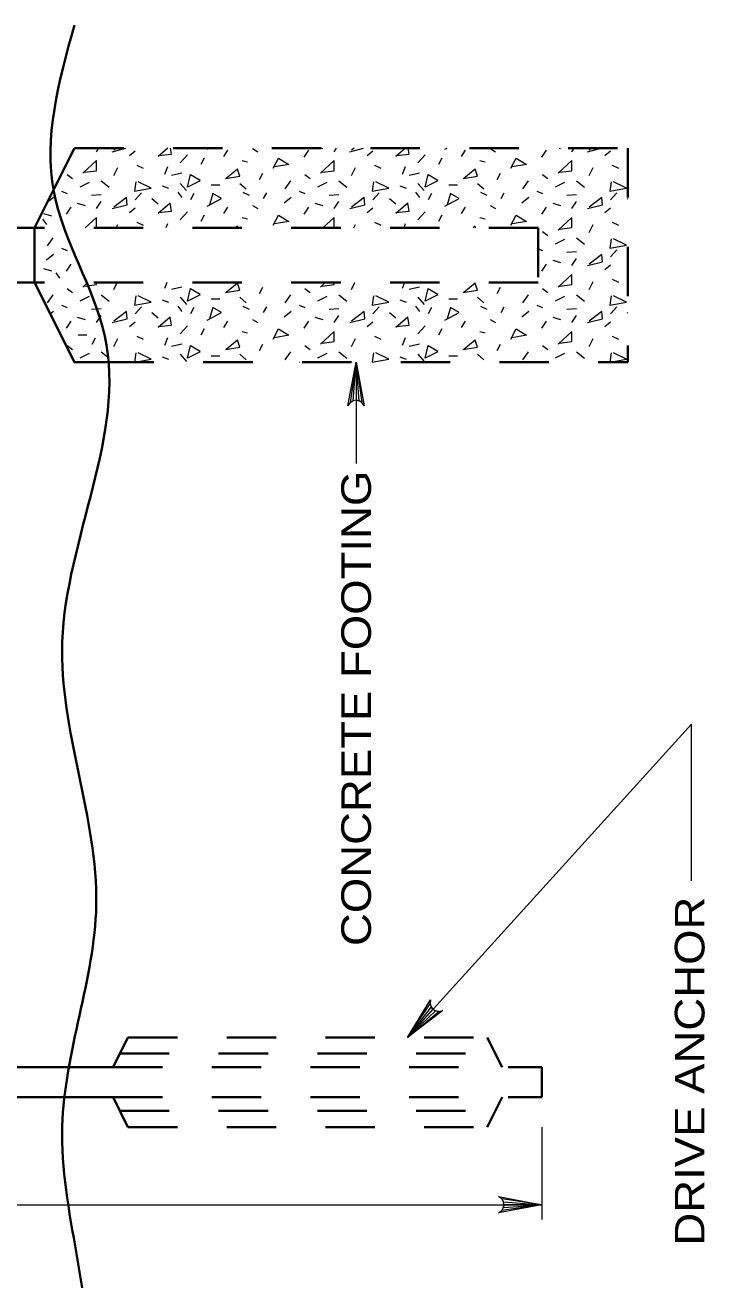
# Model space of a CAD drawing. Extents: x -46.1 to -39.3, y 101.7 to 111.8.
# Drawn here: x -43.099 to -41.722, y 109.249 to 111.793 of the extents above; entities that cross this region are included whole.
import ezdxf
from ezdxf.enums import TextEntityAlignment as Align

# ---------------------------------------------------------------- set-up
doc = ezdxf.new("R2010")
doc.units = 0
doc.header["$LTSCALE"] = 0.024
doc.linetypes.add('SHORT_DASHED', pattern=[2.7, 1.5, -1.2])
for name, color, linetype, lineweight in [('1', 7, 'Continuous', 35), ('10', 7, 'Continuous', 13), ('12', 7, 'Continuous', 53), ('6', 7, 'Continuous', 13)]:
    doc.layers.add(name, color=color, linetype=linetype, lineweight=lineweight)

msp = doc.modelspace()

# ---------------------------------------------------------------- linework, layer by layer
at = {"layer": '1', "linetype": 'SHORT_DASHED'}
for p, q in [((-42.99933, 111.54375), (-43.04037, 111.46167)), ((-42.99933, 111.54375), (-41.87812, 111.54375)), ((-41.87812, 111.54375), (-41.87812, 111.10942)), ((-42.05994, 111.38215), (-43.08015, 111.38215)), ((-42.05994, 111.38215), (-42.05994, 111.27102)), ((-42.05994, 111.27102), (-43.08015, 111.27102)), ((-42.93817, 111.10942), (-41.87812, 111.10942)), ((-42.89075, 109.74073), (-42.92104, 109.68012)), ((-42.89075, 109.74073), (-42.16348, 109.74073)), ((-42.16348, 109.74073), (-42.13317, 109.68012)), ((-42.90715, 109.7079), (-42.14706, 109.7079)), ((-42.92104, 109.68012), (-43.01042, 109.68012)), ((-42.92104, 109.68012), (-42.05235, 109.68012)), ((-42.05235, 109.68012), (-42.05235, 109.6195)), ((-42.92104, 109.6195), (-43.01954, 109.6195)), ((-42.92104, 109.6195), (-42.05235, 109.6195)), ((-42.92104, 109.6195), (-42.89075, 109.5589)), ((-42.13317, 109.6195), (-42.16348, 109.5589)), ((-42.90715, 109.59173), (-42.14706, 109.59173)), ((-42.89075, 109.5589), (-42.16348, 109.5589))]:
    msp.add_line(p, q, dxfattribs=at)
at = {"layer": '1'}
for p, q in [((-43.04037, 111.46167), (-43.08015, 111.38215)), ((-45.05994, 111.38215), (-43.08015, 111.38215)), ((-43.08015, 111.27102), (-43.08015, 111.38215)), ((-43.18873, 111.27102), (-43.08015, 111.27102)), ((-44.91852, 109.68012), (-43.01042, 109.68012)), ((-44.91852, 109.6195), (-43.01954, 109.6195))]:
    msp.add_line(p, q, dxfattribs=at)
msp.add_lwpolyline([(-43.08015, 111.27102), (-42.99933, 111.10942), (-42.93817, 111.10942)], dxfattribs=at)
msp.add_spline([(-42.99933, 111.7931), (-43.04115, 111.45546), (-42.93785, 111.16262), (-43.02392, 110.54252), (-42.95506, 110.00852), (-43.02392, 109.56067), (-42.97227, 109.0439), (-43.04115, 108.68217), (-42.95506, 108.18263), (-43.04115, 107.1491), (-42.97227, 106.47729), (-43.04115, 105.66771), (-42.97227, 104.927), (-43.00671, 104.25521), (-43.00256, 103.82462)], degree=3, dxfattribs=at)
at = {"layer": '10'}
for p, q in [((-42.42867, 111.10942), (-42.42867, 110.90398)), ((-42.05235, 109.5589), (-42.05235, 109.37133)), ((-44.98417, 109.40162), (-42.05235, 109.40162))]:
    msp.add_line(p, q, dxfattribs=at)
for points in [[(-42.42867, 111.10942), (-42.4121, 111.02115), (-42.41683, 111.02794), (-42.42275, 111.03146), (-42.42867, 111.03246), (-42.43458, 111.03146), (-42.4405, 111.02794), (-42.44521, 111.02115), (-42.42867, 111.10942), (-42.4405, 111.02794), (-42.43458, 111.03146), (-42.42867, 111.10942), (-42.42867, 111.03246), (-42.42275, 111.03146), (-42.42867, 111.10942), (-42.41683, 111.02794)], [(-41.74944, 110.05842), (-41.74944, 110.37596), (-42.32471, 109.74073)], [(-42.32471, 109.74073), (-42.27773, 109.81725), (-42.27879, 109.80904), (-42.27677, 109.80248), (-42.27306, 109.79775), (-42.268, 109.79454), (-42.26125, 109.79317), (-42.25319, 109.79504), (-42.32471, 109.74073), (-42.26125, 109.79317), (-42.268, 109.79454), (-42.32471, 109.74073), (-42.27306, 109.79775), (-42.27677, 109.80248), (-42.32471, 109.74073), (-42.27879, 109.80904)], [(-42.05235, 109.40162), (-42.14062, 109.38508), (-42.13381, 109.38979), (-42.13031, 109.39571), (-42.12929, 109.40162), (-42.13031, 109.40756), (-42.13381, 109.41348), (-42.14062, 109.41819), (-42.05235, 109.40162), (-42.13381, 109.41348), (-42.13031, 109.40756), (-42.05235, 109.40162), (-42.12929, 109.40162), (-42.13031, 109.39571), (-42.05235, 109.40162), (-42.13381, 109.38979)]]:
    msp.add_lwpolyline(points, dxfattribs=at)
at = {"layer": '6'}
for p, q in [((-42.98021, 111.54375), (-42.97729, 111.54287)), ((-42.95483, 111.53646), (-42.94998, 111.54375)), ((-42.92275, 111.53646), (-42.89504, 111.54375)), ((-42.91408, 111.54375), (-42.91954, 111.53967)), ((-42.88744, 111.52844), (-42.87621, 111.53806)), ((-42.81015, 111.54375), (-42.82969, 111.52683)), ((-42.77031, 111.53004), (-42.78475, 111.514)), ((-42.73019, 111.54127), (-42.72573, 111.54375)), ((-42.6965, 111.52683), (-42.68848, 111.53967)), ((-42.63873, 111.54287), (-42.6275, 111.53646)), ((-42.52481, 111.53967), (-42.53444, 111.52523)), ((-42.49883, 111.54375), (-42.49592, 111.54287)), ((-42.47346, 111.53646), (-42.4686, 111.54375)), ((-42.44138, 111.53646), (-42.41367, 111.54375)), ((-42.43271, 111.54375), (-42.43817, 111.53967)), ((-42.40606, 111.52844), (-42.39483, 111.53806)), ((-42.32877, 111.54375), (-42.34829, 111.52683)), ((-42.28894, 111.53004), (-42.30337, 111.514)), ((-42.24881, 111.54127), (-42.24435, 111.54375)), ((-42.21513, 111.52683), (-42.2071, 111.53967)), ((-42.15735, 111.54287), (-42.14612, 111.53646)), ((-42.04344, 111.53967), (-42.05306, 111.52523)), ((-42.01746, 111.54375), (-42.01454, 111.54287)), ((-41.99208, 111.53646), (-41.98723, 111.54375)), ((-41.96, 111.53646), (-41.93227, 111.54375)), ((-41.95133, 111.54375), (-41.95679, 111.53967)), ((-41.92469, 111.52844), (-41.91346, 111.53806)), ((-42.91954, 111.48831), (-42.91152, 111.50437)), ((-42.873, 111.50919), (-42.86017, 111.50277)), ((-42.81042, 111.50598), (-42.81683, 111.48992)), ((-42.7366, 111.52362), (-42.74302, 111.51079)), ((-42.65958, 111.51881), (-42.64835, 111.5156)), ((-42.43817, 111.48831), (-42.43015, 111.50437)), ((-42.39162, 111.50919), (-42.37879, 111.50277)), ((-42.32904, 111.50598), (-42.33546, 111.48992)), ((-42.25523, 111.52362), (-42.26165, 111.51079)), ((-42.17821, 111.51881), (-42.16698, 111.5156)), ((-41.95679, 111.48831), (-41.94875, 111.50437)), ((-41.91025, 111.50919), (-41.89742, 111.50277)), ((-43.01421, 111.48992), (-43.00298, 111.4819)), ((-42.78154, 111.49315), (-42.8024, 111.48831)), ((-42.62429, 111.48029), (-42.61787, 111.49315)), ((-42.53283, 111.48992), (-42.5216, 111.4819)), ((-42.30017, 111.49315), (-42.32102, 111.48831)), ((-42.14292, 111.48029), (-42.1365, 111.49315)), ((-42.05146, 111.48992), (-42.04023, 111.4819)), ((-43.02544, 111.45623), (-43.01421, 111.45142)), ((-42.96927, 111.47387), (-42.98854, 111.46425)), ((-42.94521, 111.47708), (-42.92917, 111.46425)), ((-42.87621, 111.43858), (-42.86337, 111.45302)), ((-42.82165, 111.46746), (-42.80881, 111.46265)), ((-42.78956, 111.45462), (-42.78154, 111.4434)), ((-42.78475, 111.47227), (-42.77192, 111.45783)), ((-42.72217, 111.46906), (-42.70452, 111.46906)), ((-42.6644, 111.47227), (-42.65156, 111.46104)), ((-42.65798, 111.45462), (-42.64515, 111.44821)), ((-42.61627, 111.44179), (-42.60985, 111.45302)), ((-42.56171, 111.47708), (-42.57294, 111.46104)), ((-42.54406, 111.45623), (-42.53283, 111.45142)), ((-42.4879, 111.47387), (-42.50715, 111.46425)), ((-42.46383, 111.47708), (-42.44779, 111.46425)), ((-42.39483, 111.43858), (-42.382, 111.45302)), ((-42.34027, 111.46746), (-42.32744, 111.46265)), ((-42.30819, 111.45462), (-42.30017, 111.4434)), ((-42.30337, 111.47227), (-42.29054, 111.45783)), ((-42.24079, 111.46906), (-42.22315, 111.46906)), ((-42.18302, 111.47227), (-42.17019, 111.46104)), ((-42.1766, 111.45462), (-42.16377, 111.44821)), ((-42.1349, 111.44179), (-42.12848, 111.45302)), ((-42.08033, 111.47708), (-42.09156, 111.46104)), ((-42.06269, 111.45623), (-42.05146, 111.45142)), ((-42.00652, 111.47387), (-42.02577, 111.46425)), ((-41.98246, 111.47708), (-41.96642, 111.46425)), ((-41.91346, 111.43858), (-41.90062, 111.45302)), ((-43.04148, 111.4434), (-43.0546, 111.43319)), ((-42.99335, 111.43217), (-42.97729, 111.42735)), ((-42.96446, 111.44821), (-42.94521, 111.44981)), ((-42.95483, 111.42094), (-42.94521, 111.43537)), ((-42.84252, 111.44179), (-42.82969, 111.43056)), ((-42.75748, 111.45142), (-42.7639, 111.43858)), ((-42.63873, 111.42735), (-42.6275, 111.42094)), ((-42.5601, 111.4434), (-42.57454, 111.43217)), ((-42.51198, 111.43217), (-42.49592, 111.42735)), ((-42.48308, 111.44821), (-42.46383, 111.44981)), ((-42.47346, 111.42094), (-42.46383, 111.43537)), ((-42.36115, 111.44179), (-42.34829, 111.43056)), ((-42.2761, 111.45142), (-42.28252, 111.43858)), ((-42.15735, 111.42735), (-42.14612, 111.42094)), ((-42.07873, 111.4434), (-42.09317, 111.43217)), ((-42.03058, 111.43217), (-42.01454, 111.42735)), ((-42.00171, 111.44821), (-41.98246, 111.44981)), ((-41.99208, 111.42094), (-41.98246, 111.43537)), ((-41.87977, 111.44179), (-41.87812, 111.44035)), ((-43.06162, 111.41142), (-43.04556, 111.4066)), ((-43.00619, 111.42415), (-43.01581, 111.40969)), ((-42.88744, 111.41292), (-42.87621, 111.42254)), ((-42.77031, 111.41452), (-42.78475, 111.39846)), ((-42.7366, 111.40808), (-42.74302, 111.39525)), ((-42.6965, 111.41131), (-42.68848, 111.42415)), ((-42.65958, 111.40327), (-42.64835, 111.40006)), ((-42.52481, 111.42415), (-42.53444, 111.40969)), ((-42.40606, 111.41292), (-42.39483, 111.42254)), ((-42.28894, 111.41452), (-42.30337, 111.39846)), ((-42.25523, 111.40808), (-42.26165, 111.39525)), ((-42.21513, 111.41131), (-42.2071, 111.42415)), ((-42.17821, 111.40327), (-42.16698, 111.40006)), ((-42.04344, 111.42415), (-42.05306, 111.40969)), ((-41.92469, 111.41292), (-41.91346, 111.42254)), ((-43.06404, 111.39973), (-43.056, 111.3885)), ((-42.91485, 111.38215), (-42.91152, 111.38883)), ((-42.873, 111.39365), (-42.86017, 111.38723)), ((-42.81042, 111.39044), (-42.81375, 111.38215)), ((-42.43348, 111.38215), (-42.43015, 111.38883)), ((-42.39162, 111.39365), (-42.37879, 111.38723)), ((-42.32904, 111.39044), (-42.33237, 111.38215)), ((-41.95679, 111.37279), (-41.94875, 111.38883)), ((-41.91025, 111.39365), (-41.89742, 111.38723)), ((-43.04308, 111.36156), (-43.05431, 111.34552)), ((-42.05146, 111.3744), (-42.04023, 111.36637)), ((-42.00652, 111.35835), (-42.02577, 111.34873)), ((-41.98246, 111.36156), (-41.96642, 111.34873)), ((-43.04148, 111.32785), (-43.05592, 111.31663)), ((-43.02544, 111.34071), (-43.01421, 111.3359)), ((-42.06269, 111.34071), (-42.05994, 111.33952)), ((-42.05994, 111.33952), (-42.05146, 111.3359)), ((-42.00171, 111.33269), (-41.98246, 111.33429)), ((-41.91346, 111.32304), (-41.90062, 111.3375)), ((-41.87977, 111.32625), (-41.87812, 111.32481)), ((-43.06179, 111.2999), (-43.04575, 111.29508)), ((-43.00619, 111.3086), (-43.01581, 111.29417)), ((-42.04344, 111.3086), (-42.05306, 111.29417)), ((-42.03058, 111.31663), (-42.01454, 111.31181)), ((-41.99208, 111.3054), (-41.98246, 111.31983)), ((-41.92469, 111.29738), (-41.91346, 111.307)), ((-43.03721, 111.29117), (-43.02919, 111.27994)), ((-41.91025, 111.27813), (-41.89742, 111.27171)), ((-43.01421, 111.25888), (-43.00298, 111.25083)), ((-42.9726, 111.27102), (-42.9821, 111.26208)), ((-42.91954, 111.25727), (-42.91265, 111.27102)), ((-42.81198, 111.27102), (-42.81683, 111.25888)), ((-42.78154, 111.26208), (-42.8024, 111.25727)), ((-42.62429, 111.24923), (-42.61787, 111.26208)), ((-42.53283, 111.25888), (-42.5216, 111.25083)), ((-42.49123, 111.27102), (-42.50073, 111.26208)), ((-42.43817, 111.25727), (-42.43127, 111.27102)), ((-42.3306, 111.27102), (-42.33546, 111.25888)), ((-42.30017, 111.26208), (-42.32102, 111.25727)), ((-42.14292, 111.24923), (-42.1365, 111.26208)), ((-42.05146, 111.25888), (-42.04023, 111.25083)), ((-41.95679, 111.25727), (-41.94875, 111.27331)), ((-43.04308, 111.24602), (-43.05431, 111.22998)), ((-43.02544, 111.22517), (-43.01421, 111.22035)), ((-42.96927, 111.24281), (-42.98854, 111.23319)), ((-42.94521, 111.24602), (-42.92917, 111.23319)), ((-42.82165, 111.2364), (-42.80881, 111.23158)), ((-42.78956, 111.22356), (-42.78154, 111.21233)), ((-42.78475, 111.24121), (-42.77192, 111.22677)), ((-42.72217, 111.238), (-42.70452, 111.238)), ((-42.6644, 111.24121), (-42.65156, 111.22998)), ((-42.65798, 111.22356), (-42.64515, 111.21715)), ((-42.56171, 111.24602), (-42.57294, 111.22998)), ((-42.54406, 111.22517), (-42.53283, 111.22035)), ((-42.4879, 111.24281), (-42.50715, 111.23319)), ((-42.46383, 111.24602), (-42.44779, 111.23319)), ((-42.34027, 111.2364), (-42.32744, 111.23158)), ((-42.30819, 111.22356), (-42.30017, 111.21233)), ((-42.30337, 111.24121), (-42.29054, 111.22677)), ((-42.24079, 111.238), (-42.22315, 111.238)), ((-42.18302, 111.24121), (-42.17019, 111.22998)), ((-42.1766, 111.22356), (-42.16377, 111.21715)), ((-42.08033, 111.24602), (-42.09156, 111.22998)), ((-42.06269, 111.22517), (-42.05146, 111.22035)), ((-42.00652, 111.24281), (-42.02577, 111.23319)), ((-41.98246, 111.24602), (-41.96642, 111.23319)), ((-43.04148, 111.21233), (-43.04819, 111.20712)), ((-42.99335, 111.2011), (-42.97729, 111.19629)), ((-42.96446, 111.21715), (-42.94521, 111.21875)), ((-42.95483, 111.18988), (-42.94521, 111.20431)), ((-42.87621, 111.20752), (-42.86337, 111.22196)), ((-42.84252, 111.21073), (-42.82969, 111.1995)), ((-42.75748, 111.22035), (-42.7639, 111.20752)), ((-42.61627, 111.21073), (-42.60985, 111.22196)), ((-42.5601, 111.21233), (-42.57454, 111.2011)), ((-42.51198, 111.2011), (-42.49592, 111.19629)), ((-42.48308, 111.21715), (-42.46383, 111.21875)), ((-42.47346, 111.18988), (-42.46383, 111.20431)), ((-42.39483, 111.20752), (-42.382, 111.22196)), ((-42.36115, 111.21073), (-42.34829, 111.1995)), ((-42.2761, 111.22035), (-42.28252, 111.20752)), ((-42.1349, 111.21073), (-42.12848, 111.22196)), ((-42.07873, 111.21233), (-42.09317, 111.2011)), ((-42.03058, 111.2011), (-42.01454, 111.19629)), ((-42.00171, 111.21715), (-41.98246, 111.21875)), ((-41.99208, 111.18988), (-41.98246, 111.20431)), ((-41.91346, 111.20752), (-41.90062, 111.22196)), ((-41.87977, 111.21073), (-41.87812, 111.20929)), ((-43.00619, 111.19308), (-43.01581, 111.17865)), ((-42.88744, 111.18185), (-42.87621, 111.19148)), ((-42.77031, 111.18346), (-42.78475, 111.1674)), ((-42.7366, 111.17704), (-42.74302, 111.16419)), ((-42.6965, 111.18025), (-42.68848, 111.19308)), ((-42.65958, 111.17221), (-42.64835, 111.169)), ((-42.63873, 111.19629), (-42.6275, 111.18988)), ((-42.52481, 111.19308), (-42.53444, 111.17865)), ((-42.40606, 111.18185), (-42.39483, 111.19148)), ((-42.28894, 111.18346), (-42.30337, 111.1674)), ((-42.25523, 111.17704), (-42.26165, 111.16419)), ((-42.21513, 111.18025), (-42.2071, 111.19308)), ((-42.17821, 111.17221), (-42.16698, 111.169)), ((-42.15735, 111.19629), (-42.14612, 111.18988)), ((-42.04344, 111.19308), (-42.05306, 111.17865)), ((-41.92469, 111.18185), (-41.91346, 111.19148)), ((-42.99158, 111.16481), (-42.97394, 111.16481)), ((-42.96321, 111.1459), (-42.95679, 111.15875)), ((-42.91954, 111.14173), (-42.91152, 111.15777)), ((-42.873, 111.16258), (-42.86017, 111.15617)), ((-42.81042, 111.15937), (-42.81683, 111.14333)), ((-42.78154, 111.14654), (-42.8024, 111.14173)), ((-42.62429, 111.13371), (-42.61787, 111.14654)), ((-42.43817, 111.14173), (-42.43015, 111.15777)), ((-42.39162, 111.16258), (-42.37879, 111.15617)), ((-42.32904, 111.15937), (-42.33546, 111.14333)), ((-42.30017, 111.14654), (-42.32102, 111.14173)), ((-42.14292, 111.13371), (-42.1365, 111.14654)), ((-41.95679, 111.14173), (-41.94875, 111.15777)), ((-41.91025, 111.16258), (-41.89742, 111.15617)), ((-43.01421, 111.14333), (-43.00298, 111.13531)), ((-42.96927, 111.12729), (-42.98854, 111.11767)), ((-42.94521, 111.1305), (-42.92917, 111.11767)), ((-42.78475, 111.12569), (-42.77192, 111.11125)), ((-42.72217, 111.12248), (-42.70452, 111.12248)), ((-42.6644, 111.12569), (-42.65156, 111.11446)), ((-42.56171, 111.1305), (-42.57294, 111.11446)), ((-42.53283, 111.14333), (-42.5216, 111.13531)), ((-42.4879, 111.12729), (-42.50715, 111.11767)), ((-42.46383, 111.1305), (-42.44779, 111.11767)), ((-42.30337, 111.12569), (-42.29054, 111.11125)), ((-42.24079, 111.12248), (-42.22315, 111.12248)), ((-42.18302, 111.12569), (-42.17019, 111.11446)), ((-42.08033, 111.1305), (-42.09156, 111.11446)), ((-42.05146, 111.14333), (-42.04023, 111.13531)), ((-42.00652, 111.12729), (-42.02577, 111.11767)), ((-41.98246, 111.1305), (-41.96642, 111.11767)), ((-42.82165, 111.12087), (-42.80881, 111.11606)), ((-42.54406, 111.10965), (-42.54352, 111.10942)), ((-42.34027, 111.12087), (-42.32744, 111.11606)), ((-42.06269, 111.10965), (-42.06215, 111.10942))]:
    msp.add_line(p, q, dxfattribs=at)
for points in [[(-42.82969, 111.52844), (-42.8024, 111.53165), (-42.80481, 111.54375)], [(-42.34829, 111.52844), (-42.32102, 111.53165), (-42.32344, 111.54375)], [(-42.9789, 111.49475), (-42.95483, 111.49796), (-42.95483, 111.51881), (-42.9821, 111.49315)], [(-42.59702, 111.50277), (-42.58577, 111.52362), (-42.56492, 111.51079), (-42.59381, 111.50598)], [(-42.49752, 111.49475), (-42.47346, 111.49796), (-42.47346, 111.51881), (-42.50073, 111.49315)], [(-42.11565, 111.50277), (-42.1044, 111.52362), (-42.08354, 111.51079), (-42.11244, 111.50598)], [(-42.01615, 111.49475), (-41.99208, 111.49796), (-41.99208, 111.51881), (-42.01935, 111.49315)], [(-42.74462, 111.47708), (-42.77031, 111.46425), (-42.7639, 111.48992), (-42.74462, 111.47869)], [(-42.69329, 111.4819), (-42.6644, 111.48671), (-42.66923, 111.50117), (-42.69169, 111.4819)], [(-42.26325, 111.47708), (-42.28894, 111.46425), (-42.28252, 111.48992), (-42.26325, 111.47869)], [(-42.21192, 111.4819), (-42.18302, 111.48671), (-42.18783, 111.50117), (-42.21031, 111.4819)], [(-42.8746, 111.47548), (-42.87781, 111.45623), (-42.84412, 111.46265), (-42.86979, 111.47548)], [(-42.39323, 111.47548), (-42.39644, 111.45623), (-42.36275, 111.46265), (-42.38842, 111.47548)], [(-41.91185, 111.47548), (-41.91506, 111.45623), (-41.88137, 111.46265), (-41.90704, 111.47548)], [(-42.92275, 111.42094), (-42.89225, 111.42896), (-42.89385, 111.4434), (-42.91954, 111.42415)], [(-42.82969, 111.41292), (-42.8024, 111.41612), (-42.8056, 111.43217), (-42.82969, 111.41131)], [(-42.73019, 111.42575), (-42.70131, 111.44179), (-42.71896, 111.45142), (-42.72537, 111.42896)], [(-42.44138, 111.42094), (-42.41087, 111.42896), (-42.41248, 111.4434), (-42.43817, 111.42415)], [(-42.34829, 111.41292), (-42.32102, 111.41612), (-42.32423, 111.43217), (-42.34829, 111.41131)], [(-42.24881, 111.42575), (-42.21994, 111.44179), (-42.23758, 111.45142), (-42.244, 111.42896)], [(-41.96, 111.42094), (-41.9295, 111.42896), (-41.9311, 111.4434), (-41.95679, 111.42415)], [(-42.95696, 111.38215), (-42.95483, 111.38242), (-42.95483, 111.40327), (-42.97729, 111.38215)], [(-42.59702, 111.38723), (-42.58577, 111.40808), (-42.56492, 111.39525), (-42.59381, 111.39044)], [(-42.47558, 111.38215), (-42.47346, 111.38242), (-42.47346, 111.40327), (-42.49592, 111.38215)], [(-42.11565, 111.38723), (-42.1044, 111.40808), (-42.08354, 111.39525), (-42.11244, 111.39044)], [(-42.01615, 111.37921), (-41.99208, 111.38242), (-41.99208, 111.40327), (-42.01935, 111.3776)], [(-42.66806, 111.38215), (-42.66923, 111.38562), (-42.67329, 111.38215)], [(-42.18669, 111.38215), (-42.18783, 111.38562), (-42.19192, 111.38215)], [(-41.91185, 111.35996), (-41.91506, 111.34071), (-41.88137, 111.34712), (-41.90704, 111.35996)], [(-41.96, 111.3054), (-41.9295, 111.31342), (-41.9311, 111.32785), (-41.95679, 111.3086)], [(-42.01615, 111.26369), (-41.99208, 111.2669), (-41.99208, 111.28775), (-42.01935, 111.26208)], [(-42.9789, 111.26369), (-42.95483, 111.2669), (-42.95483, 111.27102)], [(-42.74462, 111.24602), (-42.77031, 111.23319), (-42.7639, 111.25888), (-42.74462, 111.24762)], [(-42.69329, 111.25083), (-42.6644, 111.25567), (-42.66923, 111.2701), (-42.69169, 111.25083)], [(-42.49752, 111.26369), (-42.47346, 111.2669), (-42.47346, 111.27102)], [(-42.26325, 111.24602), (-42.28894, 111.23319), (-42.28252, 111.25888), (-42.26325, 111.24762)], [(-42.21192, 111.25083), (-42.18302, 111.25567), (-42.18783, 111.2701), (-42.21031, 111.25083)], [(-42.8746, 111.24442), (-42.87781, 111.22517), (-42.84412, 111.23158), (-42.86979, 111.24442)], [(-42.39323, 111.24442), (-42.39644, 111.22517), (-42.36275, 111.23158), (-42.38842, 111.24442)], [(-41.91185, 111.24442), (-41.91506, 111.22517), (-41.88137, 111.23158), (-41.90704, 111.24442)], [(-42.92275, 111.18988), (-42.89225, 111.1979), (-42.89385, 111.21233), (-42.91954, 111.19308)], [(-42.82969, 111.18185), (-42.8024, 111.18506), (-42.8056, 111.2011), (-42.82969, 111.18025)], [(-42.73019, 111.19469), (-42.70131, 111.21073), (-42.71896, 111.22035), (-42.72537, 111.1979)], [(-42.44138, 111.18988), (-42.41087, 111.1979), (-42.41248, 111.21233), (-42.43817, 111.19308)], [(-42.34829, 111.18185), (-42.32102, 111.18506), (-42.32423, 111.2011), (-42.34829, 111.18025)], [(-42.24881, 111.19469), (-42.21994, 111.21073), (-42.23758, 111.22035), (-42.244, 111.1979)], [(-41.96, 111.18988), (-41.9295, 111.1979), (-41.9311, 111.21233), (-41.95679, 111.19308)], [(-42.59702, 111.15617), (-42.58577, 111.17704), (-42.56492, 111.16419), (-42.59381, 111.15937)], [(-42.49752, 111.14815), (-42.47346, 111.15135), (-42.47346, 111.17221), (-42.50073, 111.14654)], [(-42.11565, 111.15617), (-42.1044, 111.17704), (-42.08354, 111.16419), (-42.11244, 111.15937)], [(-42.01615, 111.14815), (-41.99208, 111.15135), (-41.99208, 111.17221), (-42.01935, 111.14654)], [(-42.69329, 111.13531), (-42.6644, 111.14012), (-42.66923, 111.15456), (-42.69169, 111.13531)], [(-42.21192, 111.13531), (-42.18302, 111.14012), (-42.18783, 111.15456), (-42.21031, 111.13531)], [(-42.8746, 111.1289), (-42.87781, 111.10965), (-42.84412, 111.11606), (-42.86979, 111.1289)], [(-42.74462, 111.1305), (-42.77031, 111.11767), (-42.7639, 111.14333), (-42.74462, 111.1321)], [(-42.39323, 111.1289), (-42.39644, 111.10965), (-42.36275, 111.11606), (-42.38842, 111.1289)], [(-42.26325, 111.1305), (-42.28894, 111.11767), (-42.28252, 111.14333), (-42.26325, 111.1321)], [(-41.91185, 111.1289), (-41.91506, 111.10965), (-41.88137, 111.11606), (-41.90704, 111.1289)]]:
    msp.add_lwpolyline(points, dxfattribs=at)

# ---------------------------------------------------------------- texts
at = {"layer": '12', "width": 1.15}
msp.add_text('CONCRETE FOOTING', height=0.06, rotation=90, dxfattribs=at).set_placement((-42.39866, 110.88966), align=Align.RIGHT)
msp.add_text('DRIVE ANCHOR', height=0.06, rotation=90, dxfattribs=at).set_placement((-41.72314, 109.31862))

doc.saveas('drawing.dxf')
